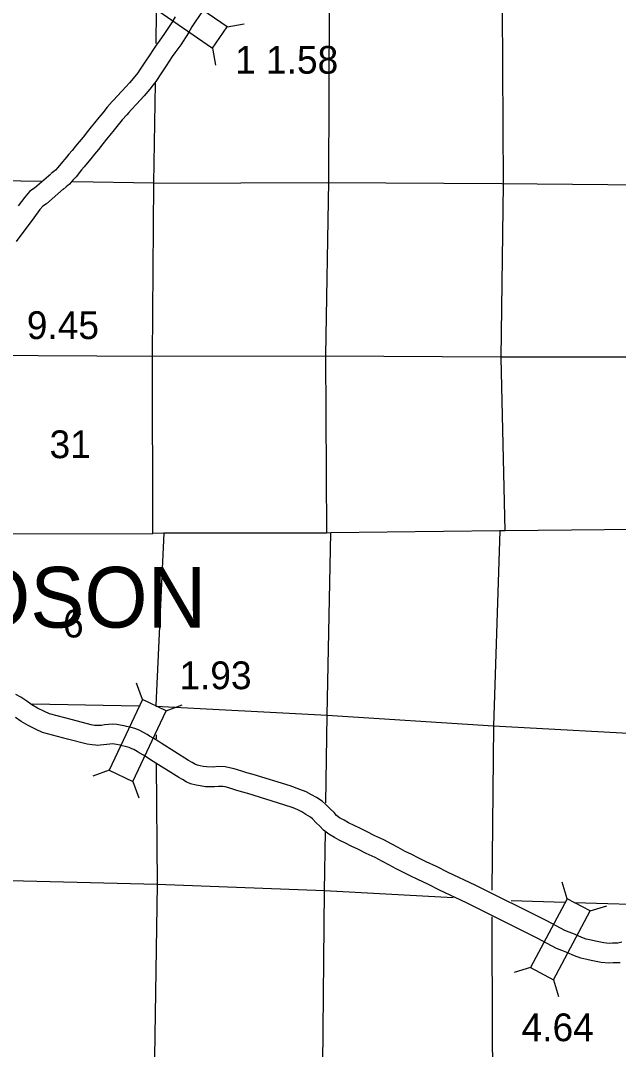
# Model space of a CAD drawing. Extents: x 369523 to 838377, y 495025 to 936819.
# Drawn here: x 640839 to 659039, y 806739 to 838052 of the extents above; entities that cross this region are included whole.
import ezdxf

# ---------------------------------------------------------------- set-up
doc = ezdxf.new("R2010")
doc.units = 0
for name, color, linetype in [('DSN_DRFT_Common-Annotations', 7, 'Continuous'), ('DSN_DRFT_Junk-No-Plot', 7, 'Continuous'), ('Level 1', 7, 'Continuous'), ('Level 11', 7, 'Continuous'), ('Level 15', 7, 'Continuous'), ('Level 21', 7, 'Continuous'), ('Level 22', 7, 'Continuous')]:
    doc.layers.add(name, color=color, linetype=linetype)

msp = doc.modelspace()

# ---------------------------------------------------------------- linework, layer by layer
at = {"layer": 'Level 1'}
for points in [[(642420, 816766), (641716, 816955), (641566, 817024), (641353, 817126), (641179, 817227), (641026, 817335), (640849, 817457), (640696, 817540)], [(642264, 816186), (641511, 816389), (641311, 816481), (641072, 816595), (640854, 816722), (640683, 816843)], [(659141, 810000), (659024, 809976), (658859, 809970), (658760, 809968), (658596, 809981), (658340, 810035), (658206, 810064), (658057, 810096), (657922, 810142), (657702, 810244), (657538, 810306), (657411, 810358), (656860, 810652), (654678, 811737), (653854, 812127), (653497, 812308), (653191, 812448), (652946, 812568), (652748, 812669), (652551, 812768), (652333, 812885), (652139, 812989), (651893, 813115), (651627, 813239), (651372, 813371), (651167, 813470), (650990, 813556), (650821, 813637), (650691, 813713), (650552, 813791), (650460, 813860), (650381, 813945), (650267, 814061), (650130, 814197), (650016, 814293), (649844, 814402), (649700, 814489), (649531, 814578), (649345, 814652), (649046, 814758), (647922, 815102), (647731, 815155), (647570, 815205), (647439, 815248), (647338, 815275), (647203, 815311), (647067, 815339), (646842, 815346), (646713, 815333), (646512, 815336), (646396, 815352), (646307, 815366), (646223, 815386), (646165, 815415), (646064, 815476), (645953, 815534), (645120, 816058), (645023, 816123), (644894, 816204), (644765, 816278), (644696, 816323), (644564, 816397), (644468, 816442), (644345, 816493), (644180, 816543), (644060, 816570), (643994, 816584), (643875, 816609), (643769, 816628), (643639, 816637), (643396, 816615), (643302, 816602), (643228, 816596), (643175, 816594), (643160, 816594), (643093, 816601), (642985, 816618), (642417, 816766)], [(659094, 809378), (658875, 809371), (658743, 809368), (658511, 809386), (658214, 809448), (658078, 809478), (657897, 809517), (657700, 809584), (657469, 809690), (657317, 809749), (657156, 809815), (656586, 810118), (654416, 811197), (653589, 811588), (653237, 811767), (652934, 811906), (652678, 812032), (652477, 812133), (652275, 812236), (652049, 812356), (651860, 812458), (651629, 812576), (651362, 812701), (651104, 812835), (650906, 812930), (650729, 813015), (650540, 813106), (650392, 813192), (650225, 813287), (650059, 813410), (649947, 813530), (649841, 813638), (649724, 813754), (649661, 813808), (649527, 813892), (649404, 813967), (649280, 814032), (649134, 814090), (648858, 814188), (647754, 814526), (647562, 814579), (647387, 814634), (647267, 814673), (647183, 814696), (647067, 814727), (646999, 814740), (646863, 814745), (646738, 814732), (646466, 814736), (646309, 814758), (646189, 814777), (646015, 814819), (645877, 814888), (645770, 814952), (645653, 815014), (644793, 815555), (644696, 815619), (644584, 815690), (644452, 815766), (644386, 815809), (644290, 815863), (644227, 815892), (644143, 815927), (644026, 815962), (643931, 815984), (643869, 815997), (643762, 816020), (643695, 816031), (643645, 816035), (643466, 816019), (643368, 816005), (643263, 815996), (643180, 815994), (643124, 815995), (643014, 816006), (642861, 816031), (642266, 816186)]]:
    msp.add_lwpolyline(points, dxfattribs=at)
at = {"layer": 'Level 11'}
for points in [[(646376, 838336), (646155, 838015), (646057, 837857), (645951, 837681), (645716, 837317), (645539, 837072), (645457, 836961), (645364, 836821), (645274, 836679), (645127, 836457), (644952, 836193), (644880, 836097), (644778, 835968), (644599, 835760), (644372, 835512), (644214, 835342), (644135, 835250), (644073, 835181), (643931, 835026), (643812, 834875), (643689, 834723), (643553, 834562), (643458, 834441), (643340, 834297), (643210, 834130), (643086, 833982), (642981, 833849), (642866, 833711), (642772, 833599), (642697, 833509), (642527, 833301), (642430, 833190), (642326, 833071), (642231, 832988), (642131, 832914)], [(645545, 838170), (645442, 837998), (645221, 837656), (645055, 837427), (644965, 837306), (644860, 837147), (644771, 837005), (644626, 836789), (644462, 836539), (644405, 836464), (644315, 836350), (644150, 836159), (643930, 835918), (643766, 835742), (643685, 835647), (643629, 835585), (643473, 835415), (643342, 835249), (643226, 835104), (643088, 834940), (642991, 834817), (642871, 834672), (642743, 834507), (642621, 834361), (642514, 834227), (642406, 834096), (642312, 833985), (642235, 833892), (642068, 833689), (641977, 833584), (641901, 833496), (641855, 833456), (641772, 833395)], [(641755, 833381), (641261, 832952), (641123, 832859), (640965, 832680), (640762, 832410)], [(642149, 832928), (641626, 832474), (641521, 832404), (641430, 832301), (641242, 832051), (640703, 831327)]]:
    msp.add_lwpolyline(points, dxfattribs=at)
at = {"layer": 'Level 15'}
for points in [[(681663, 822755), (676456, 822706), (676340, 822706), (671306, 822622), (670879, 822619), (666102, 822550), (665783, 822539), (660871, 822575), (660632, 822569), (655591, 822521), (655433, 822519), (650285, 822457), (650155, 822450), (645201, 822453), (644861, 822445)], [(639715, 817913), (639803, 822432), (644861, 822445)]]:
    msp.add_lwpolyline(points, dxfattribs=at)
at = {"layer": 'Level 21'}
for p, q in [((647127, 837861), (647647, 837957)), ((646678, 837209), (646774, 836690)), ((644549, 817385), (644370, 817882)), ((645266, 817048), (645763, 817228)), ((643540, 815234), (643043, 815055)), ((644256, 814898), (644436, 814401)), ((657482, 811327), (657327, 811832)), ((658181, 810955), (658686, 811109)), ((656365, 809230), (655860, 809076)), ((657064, 808857), (657218, 808352))]:
    msp.add_line(p, q, dxfattribs=at)
for points in [[(647127, 837861), (645171, 839209), (644722, 838557), (646678, 837209)], [(644549, 817385), (643540, 815234), (644256, 814898), (645266, 817048)], [(657482, 811327), (656365, 809230), (657064, 808857), (658181, 810955)]]:
    msp.add_lwpolyline(points, close=True, dxfattribs=at)
at = {"layer": 'Level 22'}
for points in [[(655591, 822521), (655470, 827790), (655538, 833070), (655507, 838425), (655639, 843735), (655635, 849054), (655642, 849961)], [(650256, 840056), (650231, 838543), (650217, 833139), (650120, 827864), (650155, 822450)], [(644962, 837351), (644977, 838324)], [(644861, 822445), (644858, 827825), (644895, 833107), (644943, 836147)], [(641463, 833154), (639605, 833180)], [(644895, 833107), (642427, 833141)], [(644895, 833107), (650191, 833124), (655494, 833090), (660867, 833040), (666141, 833077), (671397, 833118)], [(671373, 827930), (666109, 827861), (660868, 827807), (655459, 827812), (650116, 827840), (644858, 827825)], [(643159, 827836), (639576, 827858)], [(644858, 827825), (643159, 827836)], [(645201, 822453), (644958, 817212)], [(650133, 814244), (650176, 816917), (650285, 822457)], [(655433, 822519), (655231, 816583), (655186, 811583)], [(644443, 817191), (641195, 817245)], [(644956, 817182), (650176, 816917), (655231, 816583), (660459, 816299), (665673, 816103), (670838, 816188)], [(644962, 816312), (644963, 816188)], [(644968, 815427), (644993, 811758), (644914, 806501), (644880, 801234), (644688, 796117), (644805, 790850)], [(649841, 790685), (649920, 795884), (650054, 801119), (650045, 806270), (650091, 811568), (650119, 813367)], [(644993, 811758), (639697, 811886)], [(654003, 811348), (650091, 811568), (644993, 811758)], [(657411, 811212), (655777, 811263)], [(662158, 811064), (660424, 811118), (657694, 811203)], [(655185, 810770), (655198, 807151)], [(655198, 807151), (655202, 806144), (655123, 800881), (655037, 795647), (655161, 790535)]]:
    msp.add_lwpolyline(points, dxfattribs=at)

# ---------------------------------------------------------------- texts
at = {"layer": 'DSN_DRFT_Common-Annotations'}
msp.add_text('DONALDSON', height=1848, dxfattribs=at).set_placement((630835, 819577))
at = {"layer": 'DSN_DRFT_Junk-No-Plot'}
for s, p in [('1 1.58', (647368, 836435)), ('9.45', (641028, 828359)), ('1.93', (645672, 817703)), ('4.64', (656091, 806990))]:
    msp.add_text(s, height=844.8, dxfattribs=at).set_placement(p)
at = {"layer": 'Level 22'}
for s, height, p in [('31', 844.8, (641721, 824734)), ('6', 845, (642130, 819277))]:
    msp.add_text(s, height=height, dxfattribs=at).set_placement(p)

doc.saveas('drawing.dxf')
